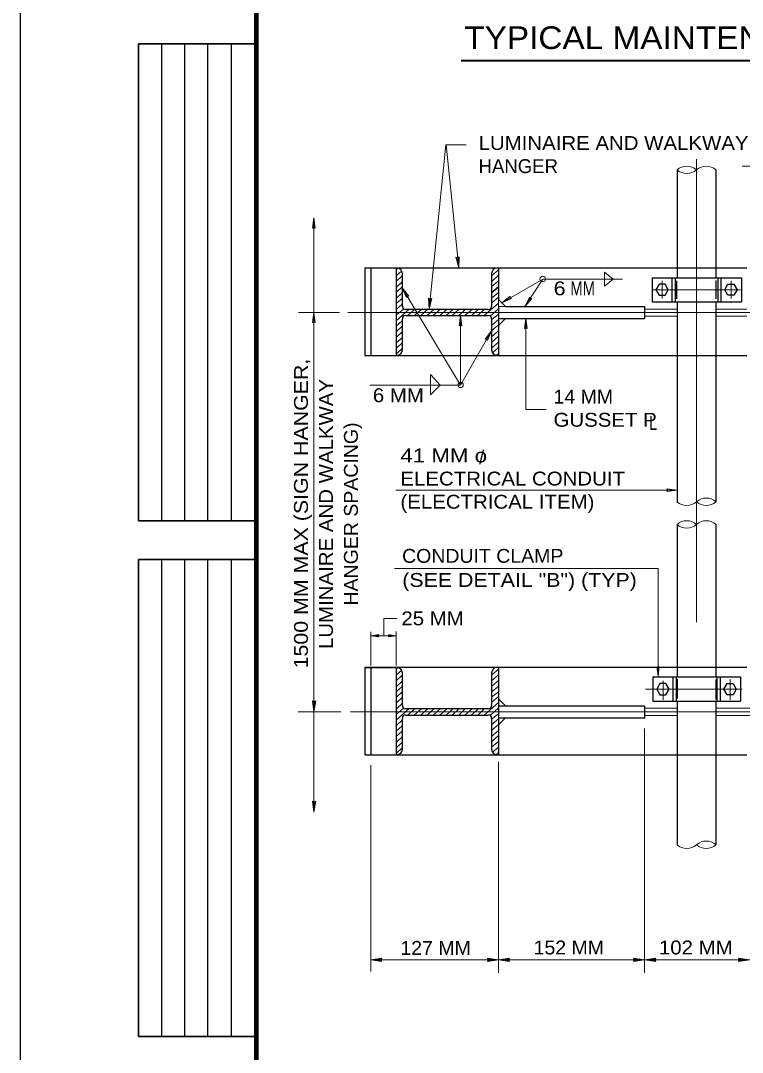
# Model space of a CAD drawing. Extents: x 312601.858 to 312602.699, y 144420.109 to 144420.704.
# Drawn here: x 312601.8578 to 312602.0138, y 144420.2326 to 144420.4555 of the extents above; entities that cross this region are included whole.
import ezdxf
from ezdxf.enums import TextEntityAlignment as Align

# ---------------------------------------------------------------- set-up
doc = ezdxf.new("R2010")
doc.units = 0
doc.header["$LTSCALE"] = 0.0012
for name, pattern in [('DOT_DASHED', [7.7, 5, -1.2, 0.3, -1.2]), ('LONG_DASHED', [7.5, 6, -1.5]), ('MEDIUM_DASHED', [4.5, 3, -1.5])]:
    doc.linetypes.add(name, pattern=pattern)
for name, color, linetype, lineweight in [('1', 7, 'Continuous', 13), ('2', 7, 'Continuous', 13), ('39', 7, 'Continuous', 13), ('60', 7, 'Continuous', 25)]:
    doc.layers.add(name, color=color, linetype=linetype, lineweight=lineweight)

msp = doc.modelspace()

# ---------------------------------------------------------------- hatches: boundary and pattern name
at = {"layer": '39'}
for points in [[(312601.9523, 144420.4043), (312601.9526, 144420.4045), (312601.9525, 144420.4021), (312601.9519, 144420.4044)], [(312601.9463, 144420.3954), (312601.9467, 144420.3955), (312601.9461, 144420.3932), (312601.946, 144420.3956)], [(312601.9463, 144420.3954), (312601.9467, 144420.3955), (312601.9461, 144420.3932), (312601.946, 144420.3956)], [(312601.9351, 144420.3226), (312601.9352, 144420.3224), (312601.9335, 144420.3226), (312601.9352, 144420.3229)], [(312601.9375, 144420.3226), (312601.9373, 144420.3229), (312601.939, 144420.3226), (312601.9373, 144420.3224)], [(312601.9212, 144420.3084), (312601.9216, 144420.3086), (312601.9212, 144420.3062), (312601.9209, 144420.3086)], [(312601.9212, 144420.2867), (312601.9216, 144420.2869), (312601.9212, 144420.2845), (312601.9209, 144420.2869)], [(312601.9357, 144420.2526), (312601.9359, 144420.2523), (312601.9335, 144420.2526), (312601.9359, 144420.253)], [(312601.9589, 144420.2526), (312601.9587, 144420.253), (312601.9611, 144420.2526), (312601.9587, 144420.2523)], [(312601.9633, 144420.2526), (312601.9635, 144420.2523), (312601.9611, 144420.2526), (312601.9635, 144420.253)], [(312601.9905, 144420.2526), (312601.9903, 144420.253), (312601.9927, 144420.2526), (312601.9903, 144420.2523)], [(312601.9949, 144420.2526), (312601.9951, 144420.2523), (312601.9927, 144420.2526), (312601.9951, 144420.253)], [(312602.0132, 144420.2526), (312602.013, 144420.253), (312602.0154, 144420.2526), (312602.013, 144420.2523)]]:
    msp.add_hatch(color=256, dxfattribs=at).paths.add_polyline_path(points)

# ---------------------------------------------------------------- linework, layer by layer
at = {"layer": '1'}
for p, q in [((312601.9498, 144420.4287), (312601.9525, 144420.4021)), ((312602.0138, 144420.4241), (312602.0301, 144420.4241)), ((312601.939, 144420.4017), (312601.9394, 144420.4021)), ((312601.939, 144420.4004), (312601.9402, 144420.4015)), ((312601.9596, 144420.4004), (312601.9611, 144420.4017)), ((312601.939, 144420.3992), (312601.9403, 144420.4004)), ((312601.939, 144420.3979), (312601.9403, 144420.3991)), ((312601.9596, 144420.3992), (312601.9611, 144420.4005)), ((312601.9596, 144420.398), (312601.9611, 144420.3993)), ((312601.9707, 144420.3997), (312601.9668, 144420.3938)), ((312601.9707, 144420.3997), (312601.9879, 144420.3997)), ((312601.939, 144420.3968), (312601.9403, 144420.398)), ((312601.939, 144420.3955), (312601.9403, 144420.3967)), ((312601.9403, 144420.3978), (312601.9529, 144420.3768)), ((312601.9596, 144420.3968), (312601.9611, 144420.3981)), ((312601.9596, 144420.3956), (312601.9611, 144420.3968)), ((312601.939, 144420.3944), (312601.9403, 144420.3955)), ((312601.958, 144420.3918), (312601.9611, 144420.3945)), ((312601.9596, 144420.3945), (312601.9611, 144420.3958)), ((312601.9179, 144420.3925), (312601.9267, 144420.3925)), ((312601.939, 144420.3931), (312601.9403, 144420.3943)), ((312601.939, 144420.3907), (312601.9418, 144420.3932)), ((312601.939, 144420.3919), (312601.9406, 144420.3932)), ((312601.9415, 144420.393), (312601.9417, 144420.3932)), ((312601.9415, 144420.3918), (312601.943, 144420.3932)), ((312601.9429, 144420.3918), (312601.9445, 144420.3932)), ((312601.9443, 144420.3918), (312601.9458, 144420.3932)), ((312601.9457, 144420.3918), (312601.9472, 144420.3932)), ((312601.9457, 144420.3918), (312601.9466, 144420.3927)), ((312601.947, 144420.3918), (312601.9486, 144420.3932)), ((312601.9484, 144420.3918), (312601.95, 144420.3932)), ((312601.9498, 144420.3918), (312601.9513, 144420.3932)), ((312601.9511, 144420.3918), (312601.9526, 144420.3932)), ((312601.9525, 144420.3918), (312601.954, 144420.3932)), ((312601.9538, 144420.3918), (312601.9555, 144420.3932)), ((312601.9553, 144420.3918), (312601.9568, 144420.3932)), ((312601.9566, 144420.3918), (312601.9581, 144420.3932)), ((312601.9593, 144420.3917), (312601.9611, 144420.3933)), ((312601.9623, 144420.3925), (312601.993, 144420.3925)), ((312601.939, 144420.3895), (312601.9403, 144420.3907)), ((312601.9529, 144420.3768), (312601.9529, 144420.3918)), ((312601.9596, 144420.3909), (312601.9611, 144420.3921)), ((312601.9596, 144420.3897), (312601.9611, 144420.391)), ((312601.939, 144420.3883), (312601.9403, 144420.3895)), ((312601.939, 144420.3871), (312601.9403, 144420.3883)), ((312601.9529, 144420.3768), (312601.9596, 144420.3885)), ((312601.9596, 144420.3885), (312601.9611, 144420.3898)), ((312601.9596, 144420.3872), (312601.9611, 144420.3885)), ((312601.939, 144420.3859), (312601.9403, 144420.387)), ((312601.939, 144420.3847), (312601.9403, 144420.3859)), ((312601.9596, 144420.386), (312601.9611, 144420.3874)), ((312601.9596, 144420.3848), (312601.9611, 144420.3861)), ((312601.939, 144420.3835), (312601.9403, 144420.3847)), ((312601.9598, 144420.3838), (312601.9611, 144420.3849)), ((312601.9606, 144420.3832), (312601.9611, 144420.3836)), ((312601.9322, 144420.3832), (312601.9391, 144420.3832)), ((312601.9333, 144420.3768), (312601.9529, 144420.3768)), ((312601.9389, 144420.3541), (312601.9997, 144420.3541)), ((312601.9335, 144420.3235), (312601.9335, 144420.3162)), ((312601.939, 144420.3236), (312601.939, 144420.3162)), ((312601.9335, 144420.3226), (312601.939, 144420.3226)), ((312601.939, 144420.3154), (312601.9394, 144420.3158)), ((312601.939, 144420.3141), (312601.9402, 144420.3152)), ((312601.9596, 144420.3141), (312601.9611, 144420.3154)), ((312601.9596, 144420.3129), (312601.9611, 144420.3142)), ((312601.939, 144420.3129), (312601.9403, 144420.3141)), ((312601.939, 144420.3116), (312601.9403, 144420.3128)), ((312601.9596, 144420.3117), (312601.9611, 144420.313)), ((312601.939, 144420.3105), (312601.9403, 144420.3117)), ((312601.939, 144420.3093), (312601.9403, 144420.3105)), ((312601.9596, 144420.3105), (312601.9611, 144420.3117)), ((312601.9596, 144420.3094), (312601.9611, 144420.3105)), ((312601.939, 144420.3081), (312601.9403, 144420.3093)), ((312601.939, 144420.3068), (312601.9403, 144420.308)), ((312601.958, 144420.3055), (312601.9611, 144420.3082)), ((312601.9596, 144420.3082), (312601.9611, 144420.3095)), ((312601.9178, 144420.3062), (312601.927, 144420.3062)), ((312601.9212, 144420.3062), (312601.9212, 144420.2845)), ((312601.939, 144420.3056), (312601.9406, 144420.307)), ((312601.939, 144420.3044), (312601.9418, 144420.3069)), ((312601.9415, 144420.3067), (312601.9417, 144420.3069)), ((312601.9415, 144420.3055), (312601.943, 144420.3069)), ((312601.9429, 144420.3055), (312601.9445, 144420.3069)), ((312601.9443, 144420.3055), (312601.9458, 144420.3069)), ((312601.9457, 144420.3055), (312601.9472, 144420.3069)), ((312601.9457, 144420.3055), (312601.9466, 144420.3064)), ((312601.947, 144420.3055), (312601.9486, 144420.3069)), ((312601.9484, 144420.3055), (312601.95, 144420.3069)), ((312601.9498, 144420.3055), (312601.9513, 144420.3069)), ((312601.9511, 144420.3055), (312601.9526, 144420.3069)), ((312601.9525, 144420.3055), (312601.954, 144420.3069)), ((312601.9538, 144420.3055), (312601.9555, 144420.3069)), ((312601.9553, 144420.3055), (312601.9568, 144420.3069)), ((312601.9566, 144420.3055), (312601.9581, 144420.3069)), ((312601.9593, 144420.3054), (312601.9611, 144420.3071)), ((312601.9596, 144420.3046), (312601.9611, 144420.3058)), ((312601.939, 144420.3032), (312601.9403, 144420.3044)), ((312601.939, 144420.302), (312601.9403, 144420.3032)), ((312601.9596, 144420.3034), (312601.9611, 144420.3047)), ((312601.9596, 144420.3022), (312601.9611, 144420.3035)), ((312601.939, 144420.3009), (312601.9403, 144420.302)), ((312601.939, 144420.2996), (312601.9403, 144420.3008)), ((312601.9596, 144420.3009), (312601.9611, 144420.3022)), ((312601.9596, 144420.2997), (312601.9611, 144420.3011)), ((312601.9927, 144420.3026), (312601.9927, 144420.2498)), ((312601.939, 144420.2984), (312601.9403, 144420.2996)), ((312601.9596, 144420.2986), (312601.9611, 144420.2998)), ((312601.9598, 144420.2975), (312601.9611, 144420.2986)), ((312601.939, 144420.2972), (312601.9403, 144420.2984)), ((312601.9606, 144420.2969), (312601.9611, 144420.2974)), ((312601.9335, 144420.2947), (312601.9335, 144420.2501)), ((312601.9611, 144420.2954), (312601.9611, 144420.2498))]:
    msp.add_line(p, q, dxfattribs=at)
at = {"layer": '1', "linetype": 'DOT_DASHED'}
for p, q in [((312602.0039, 144420.4256), (312602.0039, 144420.2754)), ((312601.9965, 144420.3993), (312601.9965, 144420.3955)), ((312602.0114, 144420.3993), (312602.0114, 144420.3955)), ((312601.9944, 144420.3974), (312602.0134, 144420.3974)), ((312601.9285, 144420.3925), (312602.0203, 144420.3925)), ((312601.9967, 144420.3129), (312601.9967, 144420.3088)), ((312602.0112, 144420.3133), (312602.0112, 144420.3088)), ((312601.9929, 144420.3111), (312602.0138, 144420.3111)), ((312601.9291, 144420.3062), (312602.114, 144420.3062))]:
    msp.add_line(p, q, dxfattribs=at)
at = {"layer": '1', "lineweight": 25}
for p, q in [((312601.9997, 144420.4233), (312601.9997, 144420.4)), ((312602.0081, 144420.4233), (312602.0081, 144420.4)), ((312601.9322, 144420.4021), (312601.9391, 144420.4021)), ((312601.9322, 144420.4021), (312601.9322, 144420.3832)), ((312601.9335, 144420.4021), (312601.9335, 144420.3832)), ((312601.939, 144420.4021), (312601.939, 144420.3832)), ((312601.9395, 144420.4021), (312601.9607, 144420.4021)), ((312601.9608, 144420.4021), (312601.9997, 144420.4021)), ((312601.9611, 144420.4021), (312601.9611, 144420.3953)), ((312602.0081, 144420.4021), (312602.0148, 144420.4021)), ((312601.9403, 144420.4009), (312601.9403, 144420.3938)), ((312601.9596, 144420.4009), (312601.9596, 144420.3938)), ((312601.9943, 144420.4), (312602.0136, 144420.4)), ((312601.9986, 144420.4), (312601.9986, 144420.3948)), ((312601.9993, 144420.4), (312601.9993, 144420.3948)), ((312602.0085, 144420.4), (312602.0085, 144420.3948)), ((312602.0092, 144420.4), (312602.0092, 144420.3948)), ((312602.0136, 144420.4), (312602.0136, 144420.3948)), ((312601.9596, 144420.3967), (312601.9611, 144420.398)), ((312601.9997, 144420.3948), (312601.9997, 144420.3516)), ((312602.0081, 144420.3948), (312602.0081, 144420.3516)), ((312601.941, 144420.3932), (312601.9589, 144420.3932)), ((312601.9611, 144420.3938), (312601.9611, 144420.3832)), ((312601.9626, 144420.3938), (312601.9927, 144420.3938)), ((312601.9927, 144420.3938), (312601.9927, 144420.3912)), ((312601.9403, 144420.3911), (312601.9403, 144420.3844)), ((312601.941, 144420.3918), (312601.9589, 144420.3918)), ((312601.9596, 144420.3911), (312601.9596, 144420.3844)), ((312601.9611, 144420.3912), (312601.9927, 144420.3912)), ((312601.9322, 144420.3832), (312601.9607, 144420.3832)), ((312601.9608, 144420.3832), (312601.9997, 144420.3832)), ((312602.0081, 144420.3832), (312602.0148, 144420.3832)), ((312601.9997, 144420.3467), (312601.9997, 144420.3138)), ((312602.0081, 144420.3467), (312602.0081, 144420.3138)), ((312601.9322, 144420.3158), (312601.9322, 144420.2969)), ((312601.9322, 144420.3158), (312601.9391, 144420.3158)), ((312601.9997, 144420.3158), (312601.9322, 144420.3158)), ((312601.9335, 144420.3158), (312601.9335, 144420.2969)), ((312601.939, 144420.3158), (312601.939, 144420.2969)), ((312601.9403, 144420.3146), (312601.9403, 144420.3076)), ((312601.9596, 144420.3146), (312601.9596, 144420.3076)), ((312601.9611, 144420.3158), (312601.9611, 144420.2969)), ((312602.0148, 144420.3158), (312602.0081, 144420.3158)), ((312601.9945, 144420.3138), (312602.0134, 144420.3138)), ((312601.9988, 144420.3138), (312601.9988, 144420.3085)), ((312601.9995, 144420.3138), (312601.9995, 144420.3085)), ((312602.0083, 144420.3138), (312602.0083, 144420.3085)), ((312602.009, 144420.3138), (312602.009, 144420.3085)), ((312602.0134, 144420.3138), (312602.0134, 144420.3085)), ((312601.9611, 144420.3075), (312601.9927, 144420.3075)), ((312601.9927, 144420.3075), (312601.9927, 144420.3048)), ((312601.9997, 144420.3085), (312601.9997, 144420.2775)), ((312602.0081, 144420.3085), (312602.0081, 144420.2775)), ((312601.941, 144420.3069), (312601.9589, 144420.3069)), ((312601.941, 144420.3055), (312601.9589, 144420.3055)), ((312601.9403, 144420.3048), (312601.9403, 144420.2981)), ((312601.9596, 144420.3048), (312601.9596, 144420.2981)), ((312601.9611, 144420.3049), (312601.9927, 144420.3049)), ((312601.9322, 144420.2969), (312601.9391, 144420.2969)), ((312601.939, 144420.2969), (312601.9997, 144420.2969)), ((312602.0081, 144420.2969), (312602.0148, 144420.2969))]:
    msp.add_line(p, q, dxfattribs=at)
at = {"layer": '1', "linetype": 'LONG_DASHED', "lineweight": 25}
for p, q in [((312601.9997, 144420.4021), (312602.0081, 144420.4021)), ((312601.9997, 144420.3832), (312602.0081, 144420.3832)), ((312602.0081, 144420.3158), (312601.9997, 144420.3158)), ((312601.9997, 144420.2969), (312602.0081, 144420.2969))]:
    msp.add_line(p, q, dxfattribs=at)
at = {"layer": '1', "linetype": 'MEDIUM_DASHED', "lineweight": 25}
for p, q in [((312601.9996, 144420.3993), (312601.9996, 144420.3954)), ((312602.0081, 144420.3994), (312602.0081, 144420.3954)), ((312601.9997, 144420.3133), (312601.9997, 144420.3091)), ((312602.0081, 144420.3132), (312602.0081, 144420.3089))]:
    msp.add_line(p, q, dxfattribs=at)
at = {"layer": '1', "linetype": 'LONG_DASHED'}
for p, q in [((312601.9927, 144420.3932), (312601.9997, 144420.3932)), ((312602.0081, 144420.3932), (312602.0148, 144420.3932)), ((312601.9927, 144420.3917), (312601.9997, 144420.3917)), ((312602.0081, 144420.3917), (312602.0148, 144420.3917)), ((312601.9927, 144420.307), (312601.9997, 144420.307)), ((312601.9927, 144420.3054), (312601.9997, 144420.3054)), ((312602.0081, 144420.307), (312602.042, 144420.307)), ((312602.0081, 144420.3054), (312602.042, 144420.3054))]:
    msp.add_line(p, q, dxfattribs=at)
at = {"layer": '1'}
for points in [[(312601.9541, 144420.4287), (312601.9497, 144420.4287), (312601.9461, 144420.3932)], [(312601.9212, 144420.4129), (312601.9212, 144420.3925), (312601.9212, 144420.3062)], [(312601.967, 144420.3912), (312601.967, 144420.3715), (312601.9714, 144420.3715)], [(312601.9386, 144420.3372), (312601.9956, 144420.3372), (312601.9956, 144420.3139)], [(312601.9335, 144420.2526), (312601.9611, 144420.2526), (312601.9927, 144420.2526), (312602.0154, 144420.2526), (312602.0985, 144420.2526)]]:
    msp.add_lwpolyline(points, dxfattribs=at)
for points in [[(312601.9209, 144420.4107), (312601.9212, 144420.4129), (312601.9215, 144420.4107), (312601.9212, 144420.4109)], [(312601.9412, 144420.3957), (312601.9403, 144420.3978), (312601.9417, 144420.396), (312601.9413, 144420.3961)], [(312601.9639, 144420.3955), (312601.9618, 144420.3946), (312601.9636, 144420.396), (312601.9636, 144420.3956)], [(312601.9683, 144420.3955), (312601.9668, 144420.3938), (312601.9678, 144420.3958), (312601.9679, 144420.3955)], [(312601.9209, 144420.3903), (312601.9212, 144420.3925), (312601.9215, 144420.3903), (312601.9212, 144420.3905)], [(312601.9526, 144420.3896), (312601.9529, 144420.3918), (312601.9532, 144420.3896), (312601.9529, 144420.3898)], [(312601.9667, 144420.389), (312601.967, 144420.3912), (312601.9673, 144420.389), (312601.967, 144420.3892)], [(312601.9582, 144420.3867), (312601.9596, 144420.3885), (312601.9587, 144420.3864), (312601.9586, 144420.3867)], [(312601.9975, 144420.3544), (312601.9997, 144420.3541), (312601.9975, 144420.3538), (312601.9977, 144420.3541)], [(312601.9958, 144420.3159), (312601.9956, 144420.3139), (312601.9953, 144420.3159), (312601.9956, 144420.3156)]]:
    msp.add_lwpolyline(points, close=True, dxfattribs=at)
at = {"layer": '1', "lineweight": 25}
for points in [[(312601.9943, 144420.4), (312601.9943, 144420.3948), (312602.0136, 144420.3948)], [(312601.9945, 144420.3138), (312601.9945, 144420.3085), (312602.0134, 144420.3085)]]:
    msp.add_lwpolyline(points, dxfattribs=at)
for points in [[(312601.9958, 144420.3962), (312601.9971, 144420.3962), (312601.9978, 144420.3974), (312601.9971, 144420.3986), (312601.9958, 144420.3986), (312601.9951, 144420.3974)], [(312602.012, 144420.3962), (312602.0107, 144420.3962), (312602.01, 144420.3974), (312602.0107, 144420.3986), (312602.012, 144420.3986), (312602.0127, 144420.3974)], [(312601.996, 144420.3099), (312601.9973, 144420.3099), (312601.998, 144420.3111), (312601.9973, 144420.3123), (312601.996, 144420.3123), (312601.9953, 144420.3111)], [(312602.0118, 144420.3099), (312602.0105, 144420.3099), (312602.0098, 144420.3111), (312602.0105, 144420.3123), (312602.0118, 144420.3123), (312602.0125, 144420.3111)]]:
    msp.add_lwpolyline(points, close=True, dxfattribs=at)
at = {"layer": '1'}
for centre in [(312601.970665, 144420.399705), (312601.9529, 144420.37684)]:
    msp.add_circle(centre, 0.000595, dxfattribs=at)
for centre, radius, start, end in [((312602.0018, 144420.420944), 0.003156, 48.29108, 131.70892), ((312602.0018, 144420.420944), 0.003156, 48.29108, 131.70892), ((312602.0018, 144420.420944), 0.003156, 48.29108, 131.70892), ((312602.006, 144420.420944), 0.003156, 48.29108, 131.70892), ((312602.006, 144420.420944), 0.003156, 48.29108, 131.70892), ((312602.006, 144420.420944), 0.003156, 48.29108, 131.70892), ((312602.0018, 144420.425656), 0.003156, 228.29108, 311.70892), ((312602.0018, 144420.425656), 0.003156, 228.29108, 311.70892), ((312602.0018, 144420.425656), 0.003156, 228.29108, 311.70892), ((312601.958935, 144420.39384), 0.00068, 359.62724, 0), ((312602.006, 144420.349244), 0.003156, 48.29108, 131.70892), ((312602.006, 144420.349244), 0.003156, 48.29108, 131.70892), ((312602.006, 144420.349244), 0.003156, 48.29108, 131.70892), ((312602.0018, 144420.353956), 0.003156, 228.29108, 311.70892), ((312602.0018, 144420.353956), 0.003156, 228.29108, 311.70892), ((312602.0018, 144420.353956), 0.003156, 228.29108, 311.70892), ((312602.006, 144420.353956), 0.003156, 228.29108, 311.70892), ((312602.006, 144420.353956), 0.003156, 228.29108, 311.70892), ((312602.006, 144420.353956), 0.003156, 228.29108, 311.70892), ((312602.0018, 144420.344344), 0.003156, 48.29108, 131.70892), ((312602.0018, 144420.344344), 0.003156, 48.29108, 131.70892), ((312602.0018, 144420.344344), 0.003156, 48.29108, 131.70892), ((312602.0018, 144420.349056), 0.003156, 228.29108, 311.70892), ((312602.0018, 144420.349056), 0.003156, 228.29108, 311.70892), ((312602.0018, 144420.349056), 0.003156, 228.29108, 311.70892), ((312602.006, 144420.344344), 0.003156, 48.29108, 131.70892), ((312602.006, 144420.344344), 0.003156, 48.29108, 131.70892), ((312602.006, 144420.344344), 0.003156, 48.29108, 131.70892), ((312601.958935, 144420.307565), 0.00068, 359.62724, 0), ((312602.0018, 144420.279856), 0.003156, 228.29108, 311.70892), ((312602.0018, 144420.279856), 0.003156, 228.29108, 311.70892), ((312602.0018, 144420.279856), 0.003156, 228.29108, 311.70892), ((312602.006, 144420.275144), 0.003156, 48.29108, 131.70892), ((312602.006, 144420.275144), 0.003156, 48.29108, 131.70892), ((312602.006, 144420.275144), 0.003156, 48.29108, 131.70892), ((312602.006, 144420.279856), 0.003156, 228.29108, 311.70892), ((312602.006, 144420.279856), 0.003156, 228.29108, 311.70892), ((312602.006, 144420.279856), 0.003156, 228.29108, 311.70892)]:
    msp.add_arc(centre, radius, start, end, dxfattribs=at)
at = {"layer": '1', "lineweight": 25}
for centre, radius, start, end in [((312601.93913, 144420.400895), 0.00119, 0, 90), ((312601.960805, 144420.400895), 0.00119, 90, 180), ((312601.941, 144420.39384), 0.00068, 180, 270), ((312601.958935, 144420.39384), 0.00068, 270, 0), ((312601.941, 144420.39112), 0.00068, 90, 180), ((312601.958935, 144420.39112), 0.00068, 0, 90), ((312601.93913, 144420.384405), 0.00119, 270, 0), ((312601.960805, 144420.384405), 0.00119, 180, 270), ((312601.93913, 144420.31462), 0.00119, 0, 90), ((312601.960805, 144420.31462), 0.00119, 90, 180), ((312601.941, 144420.307565), 0.00068, 180, 270), ((312601.958935, 144420.307565), 0.00068, 270, 0), ((312601.941, 144420.304845), 0.00068, 90, 180), ((312601.958935, 144420.304845), 0.00068, 0, 90), ((312601.93913, 144420.29813), 0.00119, 270, 0), ((312601.960805, 144420.29813), 0.00119, 180, 270)]:
    msp.add_arc(centre, radius, start, end, dxfattribs=at)
at = {"layer": '2', "lineweight": 40}
msp.add_line((312601.953, 144420.4469), (312602.1068, 144420.4469), dxfattribs=at)
at = {"layer": '2'}
for p, q in [((312601.9707, 144420.3997), (312601.9618, 144420.3946)), ((312601.9363, 144420.3226), (312601.9363, 144420.3264)), ((312601.9391, 144420.3264), (312601.9363, 144420.3264))]:
    msp.add_line(p, q, dxfattribs=at)
for points in [[(312601.984, 144420.3982), (312601.984, 144420.4012), (312601.9859, 144420.3997)], [(312601.9611, 144420.3938), (312601.9626, 144420.3938), (312601.9611, 144420.3953)], [(312601.9611, 144420.3912), (312601.9626, 144420.3912), (312601.9611, 144420.3897)], [(312601.9464, 144420.3747), (312601.9464, 144420.3791), (312601.9485, 144420.3768)], [(312601.9611, 144420.3075), (312601.9626, 144420.3075), (312601.9611, 144420.309)], [(312601.9611, 144420.3049), (312601.9626, 144420.3049), (312601.9611, 144420.3034)]]:
    msp.add_lwpolyline(points, close=True, dxfattribs=at)
at = {"layer": '39', "lineweight": 25}
msp.add_line((312601.8578, 144420.1095), (312601.8578, 144420.7035), dxfattribs=at)
at = {"layer": '39', "lineweight": 158}
msp.add_line((312601.9088, 144420.1247), (312601.9088, 144420.6645), dxfattribs=at)
at = {"layer": '39'}
for points in [[(312601.9523, 144420.4043), (312601.9526, 144420.4045), (312601.9525, 144420.4021), (312601.9519, 144420.4044)], [(312601.9463, 144420.3954), (312601.9467, 144420.3955), (312601.9461, 144420.3932), (312601.946, 144420.3956)], [(312601.9463, 144420.3954), (312601.9467, 144420.3955), (312601.9461, 144420.3932), (312601.946, 144420.3956)], [(312601.9351, 144420.3226), (312601.9352, 144420.3224), (312601.9335, 144420.3226), (312601.9352, 144420.3229)], [(312601.9375, 144420.3226), (312601.9373, 144420.3229), (312601.939, 144420.3226), (312601.9373, 144420.3224)], [(312601.9212, 144420.3084), (312601.9216, 144420.3086), (312601.9212, 144420.3062), (312601.9209, 144420.3086)], [(312601.9212, 144420.2867), (312601.9216, 144420.2869), (312601.9212, 144420.2845), (312601.9209, 144420.2869)], [(312601.9357, 144420.2526), (312601.9359, 144420.2523), (312601.9335, 144420.2526), (312601.9359, 144420.253)], [(312601.9589, 144420.2526), (312601.9587, 144420.253), (312601.9611, 144420.2526), (312601.9587, 144420.2523)], [(312601.9633, 144420.2526), (312601.9635, 144420.2523), (312601.9611, 144420.2526), (312601.9635, 144420.253)], [(312601.9905, 144420.2526), (312601.9903, 144420.253), (312601.9927, 144420.2526), (312601.9903, 144420.2523)], [(312601.9949, 144420.2526), (312601.9951, 144420.2523), (312601.9927, 144420.2526), (312601.9951, 144420.253)], [(312602.0132, 144420.2526), (312602.013, 144420.253), (312602.0154, 144420.2526), (312602.013, 144420.2523)]]:
    msp.add_lwpolyline(points, close=True, dxfattribs=at)
at = {"layer": '60'}
for p, q in [((312601.8883, 144420.3475), (312601.8883, 144420.4505)), ((312601.8933, 144420.3475), (312601.8933, 144420.4505)), ((312601.8983, 144420.3475), (312601.8983, 144420.4505)), ((312601.9034, 144420.3475), (312601.9034, 144420.4505)), ((312601.8883, 144420.2361), (312601.8883, 144420.3391)), ((312601.8933, 144420.2361), (312601.8933, 144420.3391)), ((312601.8983, 144420.2361), (312601.8983, 144420.3391)), ((312601.9034, 144420.2361), (312601.9034, 144420.3391))]:
    msp.add_line(p, q, dxfattribs=at)
at = {"layer": '60', "lineweight": 35}
for points in [[(312601.9084, 144420.3475), (312601.8833, 144420.3475), (312601.8833, 144420.4505), (312601.9084, 144420.4505)], [(312601.9084, 144420.2361), (312601.8833, 144420.2361), (312601.8833, 144420.3391), (312601.9084, 144420.3391)]]:
    msp.add_lwpolyline(points, dxfattribs=at)

# ---------------------------------------------------------------- texts
at = {"layer": '2'}
for s, height, width, p in [('TYPICAL MAINTENANCE WALKWAY DETAIL', 0.0049, 1.1, (312601.9537, 144420.4494)), ('LUMINAIRE AND WALKWAY', 0.003, 1.1, (312601.9568, 144420.4276)), ('14 MM', 0.003, 1.05, (312601.973, 144420.3728)), ('GUSSET P', 0.003, 1.1, (312601.973, 144420.3678)), ('41 MM o', 0.003, 1.2, (312601.9399, 144420.3601)), ('ELECTRICAL CONDUIT', 0.003, 1.1, (312601.9399, 144420.3551)), ('(ELECTRICAL ITEM)', 0.003, 1.1, (312601.9399, 144420.3501))]:
    msp.add_text(s, height=height, dxfattribs=dict(at, width=width)).set_placement(p)
msp.add_text('HANGER ', height=0.003, dxfattribs=at).set_placement((312601.9568, 144420.4226))
for s, width, p in [('6 ', 1.15, (312601.97495, 144420.3962)), ('MM', 0.8, (312601.9793, 144420.3962)), ('6 MM', 1.1, (312601.93945, 144420.3731)), ('L', 0.75, (312601.99455, 144420.3671)), ('CONDUIT CLAMP', 1.05, (312601.9577, 144420.3384)), ('(SEE DETAIL "B") (TYP)', 1.15, (312601.96565, 144420.3332)), ('25 MM', 1.1, (312601.94685, 144420.3249)), ('127 MM', 1.05, (312601.9475, 144420.2537)), ('152 MM', 1.05, (312601.9763, 144420.2538)), ('102 MM', 1.1, (312602.00375, 144420.2538))]:
    msp.add_text(s, height=0.003, dxfattribs=dict(at, width=width)).set_placement(p, align=Align.CENTER)
for s, width, p in [('1500 MM MAX (SIGN HANGER,', 1.15, (312601.9199, 144420.34905)), ('LUMINAIRE AND WALKWAY', 1.1, (312601.9253, 144420.34895)), ('HANGER SPACING)', 1.05, (312601.9307, 144420.34895))]:
    msp.add_text(s, height=0.003, rotation=90, dxfattribs=dict(at, width=width)).set_placement(p, align=Align.CENTER)
msp.add_text('/', height=0.003, dxfattribs=at).set_placement((312601.95745, 144420.3597), align=Align.CENTER)

doc.saveas('drawing.dxf')
